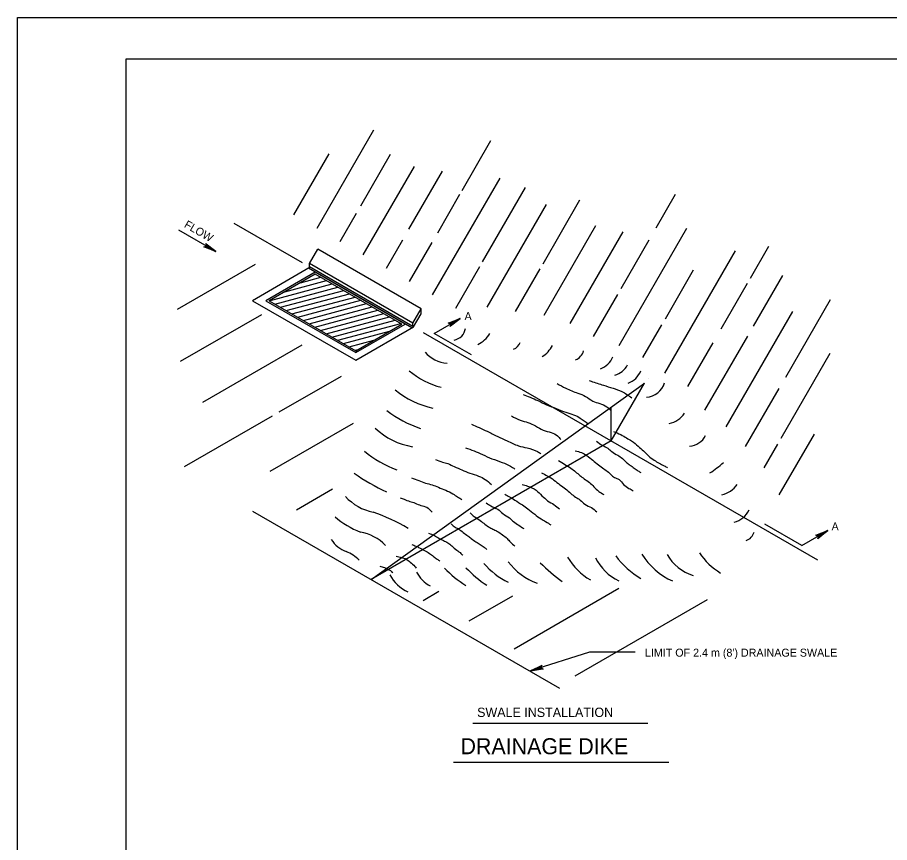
# Model space of a CAD drawing. Extents: x 69 to 973, y -48 to 546.
# Drawn here: x 68.6 to 382.3, y 249 to 546 of the extents above; entities that cross this region are included whole.
import ezdxf

# ---------------------------------------------------------------- set-up
doc = ezdxf.new("R2010")
doc.units = 0
for name, color, linetype in [('1', 7, 'Continuous'), ('2', 7, 'Continuous'), ('3', 7, 'Continuous'), ('PLT-BNDY', 7, 'Continuous')]:
    doc.layers.add(name, color=color, linetype=linetype)

msp = doc.modelspace()

# ---------------------------------------------------------------- linework, layer by layer
at = {"layer": '1'}
msp.add_lwpolyline([(893.57, -33.04), (893.57, 530.96), (107.57, 530.96), (107.57, -33.04), (893.57, -33.04), (893.57, -6.68), (693.57, -6.68), (693.57, 58), (893.57, 58), (893.57, 86.96), (693.57, 86.96), (693.57, -33.04), (772.37, -33.04), (772.37, -6.68), (772.37, -33.04), (849.37, -33.04), (849.37, -6.68), (849.37, -19), (893.57, -19)], dxfattribs=at)
at = {"layer": '2'}
for p, q in [((176.37, 470.1), (196.82, 505.53)), ((228.52, 483.64), (238.91, 501.63)), ((168.05, 474.9), (180.7, 496.81)), ((192.08, 478.12), (202.81, 496.7)), ((193, 460.5), (211.37, 492.32)), ((209.39, 469.7), (221.48, 490.63)), ((217.94, 446.1), (242.22, 488.16)), ((235.86, 457.94), (251.37, 484.8)), ((219.75, 468.43), (227.75, 482.3)), ((257.67, 457.31), (270.93, 480.28)), ((298.35, 470.18), (305.34, 482.29)), ((237.54, 441.66), (258.9, 478.65)), ((184.68, 465.3), (190.54, 475.45)), ((171.12, 457.64), (146.58, 471.81)), ((258.07, 438.81), (276.67, 471.04)), ((139.97, 461.72), (126.58, 469.44)), ((267.4, 435.77), (286.48, 468.82)), ((284.99, 427.85), (309.4, 470.12)), ((201.31, 455.7), (207.21, 465.92)), ((209.62, 450.9), (217.73, 464.95)), ((285.8, 448.44), (295.87, 465.88)), ((173.63, 457.4), (176.63, 462.59)), ((213.8, 441.13), (176.63, 462.59)), ((301.46, 417.97), (326.88, 462)), ((332.29, 452.17), (338.9, 463.61)), ((126.09, 440.98), (154.21, 457.21)), ((210.5, 434.21), (173.33, 455.68)), ((173.63, 456.2), (173.63, 457.4)), ((210.8, 435.93), (173.63, 457.4)), ((210.8, 434.73), (173.63, 456.2)), ((226.25, 441.3), (234.92, 456.31)), ((247.76, 440.16), (256.6, 455.46)), ((301.66, 437.51), (311.82, 455.12)), ((170.34, 450.49), (177.7, 452.46)), ((333.35, 434.8), (343.91, 453.09)), ((159.1, 444), (181.81, 450.09)), ((161.16, 442.81), (183.87, 448.9)), ((164.72, 447.25), (179.75, 451.27)), ((321.75, 433.92), (331.22, 450.32)), ((163.21, 441.62), (185.93, 447.71)), ((165.27, 440.44), (187.98, 446.52)), ((275.81, 431.14), (284.56, 446.29)), ((167.33, 439.25), (190.04, 445.33)), ((169.39, 438.06), (192.1, 444.15)), ((171.44, 436.87), (194.16, 442.96)), ((344.96, 416.52), (361.07, 444.41)), ((173.5, 435.68), (196.21, 441.77)), ((175.56, 434.5), (198.27, 440.58)), ((177.62, 433.31), (200.33, 439.39)), ((210.8, 435.93), (213.8, 441.13)), ((213.8, 439.24), (213.8, 441.13)), ((323.55, 398.63), (347.5, 440.12)), ((127.17, 422.2), (156.43, 439.09)), ((179.67, 432.12), (202.39, 438.21)), ((181.73, 430.93), (204.44, 437.02)), ((211.1, 434.56), (213.8, 439.24)), ((218.53, 432.2), (227.89, 437.6)), ((183.79, 429.75), (206.5, 435.83)), ((185.85, 428.56), (202.37, 432.99)), ((210.8, 434.73), (210.8, 435.93)), ((293.59, 423.54), (300.42, 435.36)), ((214.59, 432.55), (356.4, 350.67)), ((231.92, 424.47), (218.53, 432.2)), ((315.88, 404.54), (331.29, 431.23)), ((135.22, 407.45), (171.01, 428.11)), ((187.9, 427.37), (196.75, 429.74)), ((309.74, 413.11), (318.84, 428.87)), ((189.96, 426.18), (191.13, 426.49)), ((343.36, 394.54), (361.01, 425.11)), ((162.78, 403.96), (185.18, 416.89)), ((195.8, 343.63), (294.2, 414.29)), ((282.2, 393.51), (294.2, 414.29)), ((295.51, 416.01), (295.51, 416.01)), ((330.54, 391.53), (342.6, 412.43)), ((282.2, 393.51), (282.2, 405.68)), ((128.7, 384.28), (160.33, 402.54)), ((159.48, 382.65), (189.45, 399.96)), ((342.64, 374.1), (355.29, 396.01)), ((282.2, 393.51), (195.8, 343.63)), ((337.18, 383.83), (342.07, 392.31)), ((169.01, 368.76), (181.96, 376.24)), ((153.17, 368.24), (263.56, 304.51)), ((350.78, 355.85), (337.39, 363.58)), ((350.78, 355.85), (360.13, 361.25)), ((214.5, 336.14), (220.16, 339.41)), ((247.28, 318.72), (284.97, 340.48)), ((231.04, 328.74), (246.75, 337.81)), ((269.25, 308.96), (316.81, 336.43)), ((274.37, 317.51), (253.14, 310.72))]:
    msp.add_line(p, q, dxfattribs=at)
for points in [[(136.47, 464.37), (136.45, 464.01), (139.97, 461.72), (136.47, 464.37), (136.37, 464.65), (139.97, 461.72), (136.23, 463.63), (135.94, 463.44), (139.97, 461.72), (135.63, 463.38), (135.94, 463.44)], [(173.92, 456.03), (153.1, 444), (190.27, 422.54), (211.1, 434.56)], [(175.73, 454.29), (157.9, 444), (190.27, 425.31), (208.1, 435.6), (175.73, 454.29)], [(175.73, 453.6), (175.73, 453.6), (159.1, 444), (190.27, 426), (206.9, 435.6), (175.73, 453.6)], [(223.84, 435.89), (224.14, 435.7), (227.89, 437.6), (223.84, 435.89), (223.55, 435.95), (227.89, 437.6), (224.36, 435.32), (224.38, 434.98), (227.89, 437.6), (224.28, 434.68), (224.38, 434.98)], [(356.08, 359.54), (356.38, 359.35), (360.13, 361.25), (356.08, 359.54), (355.79, 359.6), (360.13, 361.25), (356.6, 358.97), (356.63, 358.63), (360.13, 361.25), (356.52, 358.33), (356.63, 358.63)], [(290.82, 317.51), (274.37, 317.51)], [(257.46, 311.53), (257.21, 311.78), (253.14, 310.72), (257.46, 311.53), (257.73, 311.42), (253.14, 310.72), (257.07, 312.2), (257.12, 312.54), (253.14, 310.72), (257.29, 312.81), (257.12, 312.54)]]:
    msp.add_lwpolyline(points, dxfattribs=at)
for centre, radius, start, end in [((224.94, 434.62), 4.83, 278.7322, 352.9257), ((229.31, 437.87), 10.83, 296.4976, 328.6597), ((245.65, 430.22), 3.97, 290.552, 342.2447), ((251.88, 432.55), 10.24, 302.0829, 333.1976), ((224.12, 433.2), 11.77, 220.8394, 265.1683), ((267.29, 427.42), 5.18, 293.7565, 342.9707), ((275.46, 426.84), 7.92, 291.3226, 337.1065), ((281.55, 424.18), 7.25, 285.3952, 333.0183), ((227.89, 440.06), 28.09, 229.218, 255.8801), ((285.86, 421.31), 7.39, 288.8616, 339.6095), ((294.29, 416.61), 7.41, 274.7891, 342.538), ((224.63, 436.29), 31.63, 230.3966, 257.9943), ((226.89, 437.71), 41.85, 232.6223, 251.4525), ((301.15, 408.42), 8.87, 282.5375, 326.2208), ((214.58, 415.94), 24.78, 225.7889, 261.081), ((309.7, 398.79), 7.22, 275.4173, 332.6203), ((219.71, 421.95), 41.51, 230.7003, 249.3369), ((290.22, 422.98), 49.34, 303.8379, 310.9659), ((236.92, 450.33), 83.13, 235.3823, 244.6575), ((320.09, 382.82), 8.87, 282.5375, 326.2208), ((200.32, 386.17), 18.68, 222.5109, 258.3669), ((173.22, 301.21), 70.64, 59.4787, 70.7116), ((324.06, 372.64), 8.7, 285.3952, 333.0183), ((204.15, 391.13), 32.78, 229.4096, 248.1102), ((190.61, 363.86), 10.83, 212.5736, 249.7166), ((188.64, 343.38), 17.65, 45.3795, 79.2585), ((329.06, 362.12), 4.77, 290.552, 342.2447), ((182.22, 341.87), 12.7, 43.1783, 68.5941), ((286.78, 363.78), 23.62, 210.7136, 239.2844), ((293.07, 359.68), 18.47, 206.3362, 243.6638), ((306.98, 368.97), 28.62, 215.8924, 240.4663), ((314.57, 365.95), 25.07, 211.6626, 245.6146), ((316.12, 360.24), 15.75, 208.7246, 253.4199), ((334.57, 367.31), 24.99, 214.1772, 238.5723), ((257.45, 367.44), 27.7, 220.4974, 243.5334), ((263.75, 364.17), 23.39, 217.1397, 249.3312), ((312.35, 407.15), 80.08, 225.8499, 233.3717), ((214.54, 351.35), 13.36, 206.5052, 245.6556), ((222.95, 352), 12.2, 207.617, 241.008), ((257.52, 382.68), 49.67, 224.6396, 236.1057), ((258.2, 373.86), 38.38, 222.5671, 237.285)]:
    msp.add_arc(centre, radius, start, end, dxfattribs=at)
for points in [[(262.69, 414.16), (265.83, 412.52), (270.16, 410.72), (272.99, 409.53), (275.53, 407.89), (278.07, 406.99), (280.61, 405.8), (281.95, 404.6)], [(274.26, 415.31), (274.93, 415.05), (279.41, 413.56), (282.84, 412.52), (285.98, 411.32), (289.56, 409.08)], [(250.45, 410.28), (252.99, 409.23), (255.82, 408.04), (258.96, 406.54), (262.39, 405.2), (265.83, 403.86), (268.66, 402.96), (271.05, 401.77), (273.89, 399.68)], [(246.27, 402.51), (249.4, 401.02), (252.24, 400.12), (254.93, 398.93), (257.76, 397.44), (260.6, 396.54), (262.84, 395.35), (264.03, 394)], [(231.94, 399.53), (234.63, 398.33), (237.61, 396.99), (241.19, 395.2), (244.78, 393.56), (248.81, 391.77), (251.94, 391.02), (255.67, 389.68), (256.87, 388.93)], [(282.96, 396.98), (285.59, 395.79), (287.74, 394.59), (289.53, 393.52), (291.92, 391.61), (293.83, 389.94), (295.62, 388.15), (297.65, 386.59), (301.23, 384.56), (302.43, 383.85)], [(276.87, 393.4), (279.02, 391.97), (280.93, 390.89), (282.36, 389.7), (284.51, 388.38), (286.19, 387.19), (287.74, 385.76), (288.93, 384.8), (290.49, 383.73), (291.8, 382.77), (292.87, 382.17)], [(229.7, 391.02), (232.83, 389.97), (235.82, 388.63), (239.25, 387.14), (242.99, 385.79), (245.97, 384.45), (247.46, 383.41)], [(269.23, 389.94), (271.5, 389.34), (273.41, 388.26), (275.56, 386.59), (277.59, 384.92), (279.5, 383.49), (281.17, 382.29), (282.13, 381.34), (283.32, 380.38), (284.99, 379.67), (286.66, 377.87), (288.58, 376.44), (290.13, 375.61)], [(218.95, 386.84), (221.49, 385.94), (223.43, 385.35), (225.67, 384.3), (228.5, 383.11), (231.34, 381.91), (234.48, 380.87), (236.86, 379.67), (239.1, 377.88)], [(263.26, 386.47), (265.53, 385.04), (267.67, 383.73), (269.35, 382.41), (270.9, 381.1), (272.45, 379.9), (274.36, 378.59), (275.92, 377.04), (277.71, 375.37), (279.5, 374.29)], [(210.29, 380.27), (212.98, 379.23), (215.37, 378.33), (217.76, 377.73), (220, 376.84), (222.68, 375.79), (225.22, 374.45), (228.5, 372.36)], [(257.05, 382.05), (259.2, 380.98), (261.58, 379.43), (263.73, 377.76), (265.76, 376.32), (267.67, 374.65), (269.35, 373.34), (271.02, 372.26), (272.69, 370.71), (275.08, 369.51), (276.99, 367.96)], [(250.12, 377.87), (252.03, 377.28), (255.13, 375.84), (257.28, 373.81), (259.31, 372.02), (261.58, 370.59), (263.61, 369.04)], [(243.91, 374.41), (245.58, 373.46), (247.49, 372.26), (250.24, 370.47), (252.15, 369.04), (254.66, 367.13), (256.93, 365.45), (258.6, 364.5), (260.51, 363.3)], [(206.26, 373.1), (207.75, 372.51), (209.69, 371.76), (211.64, 371.16), (213.73, 370.27), (215.82, 369.67), (217.76, 367.88)], [(237.22, 371.19), (238.89, 370.11), (241.4, 368.92), (243.19, 367.36), (245.58, 365.81), (247.01, 364.5), (248.92, 363.18), (250.72, 361.99)], [(231.49, 367.6), (232.92, 366.29), (235.07, 364.86), (236.74, 363.54), (238.53, 362.35), (239.97, 361.63), (241.28, 360.92), (243.07, 359.72), (244.74, 358.41), (245.94, 357.09), (247.49, 355.66)], [(224.56, 363.66), (225.64, 362.71), (227.19, 361.87), (228.98, 360.56), (230.65, 359.36), (231.85, 358.41), (233.52, 357.21), (235.07, 356.26), (236.5, 355.3), (237.46, 354.47)], [(216.44, 360.32), (218.59, 359.48), (220.14, 358.53), (221.81, 357.69), (223.37, 356.85), (224.8, 355.78), (226.59, 354.23), (228.14, 353.03), (228.62, 352.56), (228.86, 352.44)], [(210.47, 356.26), (211.9, 355.66), (213.22, 355.06), (215.01, 354.11), (216.8, 353.03), (218.23, 351.96), (219.55, 351), (220.5, 350.29)], [(204.86, 352.08), (206.65, 351.6), (208.44, 351), (209.87, 349.93), (211.54, 348.38), (212.02, 347.78)], [(198.89, 348.4), (200.58, 348.01), (201.88, 347.41), (203.57, 346.21)]]:
    msp.add_spline(points, degree=3, dxfattribs=at)
at = {"layer": '3'}
for p, q in [((232.34, 291.91), (295.34, 291.91)), ((225.42, 277.93), (302.96, 277.93))]:
    msp.add_line(p, q, dxfattribs=at)
at = {"layer": 'PLT-BNDY'}
msp.add_lwpolyline([(68.57, 545.96), (909.57, 545.96), (909.57, -48.04), (68.57, -48.04)], close=True, dxfattribs=at)

# ---------------------------------------------------------------- texts
at = {"layer": '3'}
msp.add_text('FLOW', height=2.88, rotation=329.9979, dxfattribs=at).set_placement((128.3, 470.6))
for s, height, p in [('A', 2.88, (229.41, 437.01)), ('A', 2.88, (361.45, 361.31)), ("LIMIT OF 2.4 m (8') DRAINAGE SWALE", 2.88, (294.31, 315.87)), ('SWALE INSTALLATION', 3.36, (233.94, 294.16)), ('DRAINAGE DIKE', 5.76, (227.96, 280.76))]:
    msp.add_text(s, height=height, dxfattribs=at).set_placement(p)

doc.saveas('drawing.dxf')
